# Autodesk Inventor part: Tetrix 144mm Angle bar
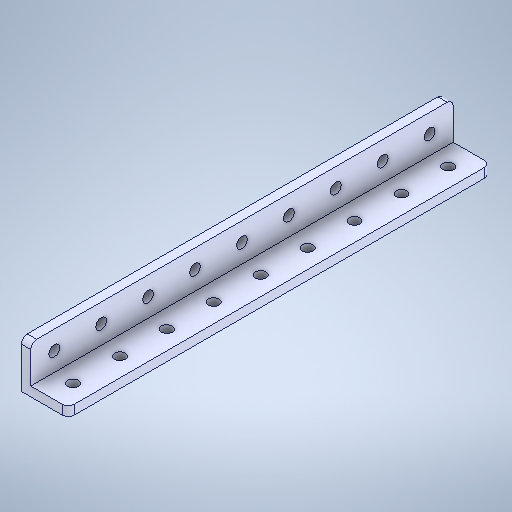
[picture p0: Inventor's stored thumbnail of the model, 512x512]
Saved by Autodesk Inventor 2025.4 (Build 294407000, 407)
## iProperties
Created: 2021-10
Part Number: Tetrix 144mm Angle bar
Material: Genérico
Document SubType Name: Modeling
Designer: usuario
Density: 1 g/cm^3
Appearance: Valor por defecto
Author: usuario
Sending System: SolidWorks 2016
Last Author: LENOVO
Last Saved: 2021-10-21
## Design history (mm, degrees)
fillet "Fillet1"
node "Plane1"
node "Sólido1"
